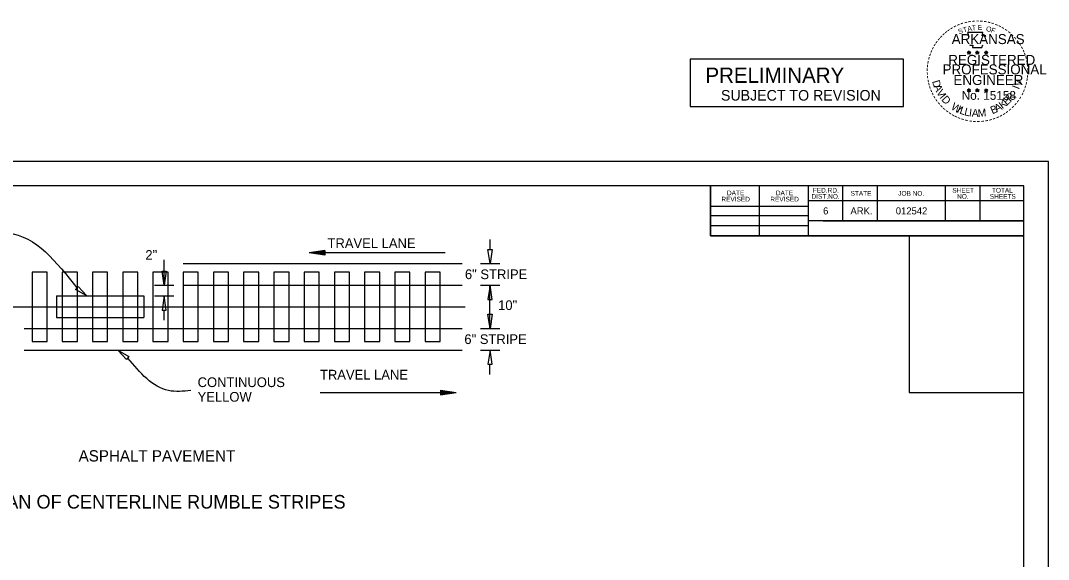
# Model space of a CAD drawing. Extents: x 1371343 to 1376243, y 378740 to 382184.
# Drawn here: x 1371995 to 1373043, y 381635 to 382184 of the extents above; entities that cross this region are included whole.
import ezdxf

# ---------------------------------------------------------------- set-up
doc = ezdxf.new("R2010")
doc.units = 0
for name, color, linetype in [('Default', 7, 'Continuous'), ('R_Border PE', 7, 'Continuous'), ('SHET_Annotations', 7, 'Continuous'), ('SHET_Border-Lines', 7, 'Continuous'), ('SHET_Border-Text', 7, 'Continuous'), ('SHET_Stamp-PE-Chief-Eng', 7, 'Continuous'), ('SHET_Stamp-Prelim', 7, 'Continuous'), ('SHET_Stamp-Seal', 7, 'Continuous')]:
    doc.layers.add(name, color=color, linetype=linetype)

msp = doc.modelspace()

# ---------------------------------------------------------------- linework, layer by layer
at = {"layer": 'Default'}
for p, q in [((1372473.6, 381960.9), (1372473.6, 381950.6)), ((1372305.1, 381949.6), (1372289.3, 381947.3)), ((1372427.9, 381947.3), (1372289.3, 381947.3)), ((1372305.1, 381944.9), (1372289.3, 381947.3)), ((1372305.1, 381949.2), (1372292, 381947.3)), ((1372305.1, 381945.3), (1372292, 381947.3)), ((1372305.1, 381948.8), (1372294.7, 381947.3)), ((1372305.1, 381945.7), (1372294.7, 381947.3)), ((1372305.1, 381948.4), (1372297.3, 381947.3)), ((1372305.1, 381946.1), (1372297.3, 381947.3)), ((1372305.1, 381948), (1372300, 381947.3)), ((1372305.1, 381946.5), (1372300, 381947.3)), ((1372305.1, 381947.6), (1372302.6, 381947.3)), ((1372305.1, 381946.9), (1372302.6, 381947.3)), ((1372305.1, 381949.6), (1372305.1, 381944.9)), ((1372141.5, 381914.2), (1372141.5, 381940.2)), ((1372161, 381936.2), (1372445.4, 381936.2)), ((1372463.8, 381936.2), (1372483.5, 381936.2)), ((1372131.6, 381914.2), (1372151.4, 381914.2)), ((1372161, 381914.2), (1372445.4, 381914.2)), ((1372463.8, 381914.2), (1372483.5, 381914.2)), ((1372473.6, 381870.1), (1372473.6, 381914.2)), ((1372031.7, 381903.2), (1372031.7, 381881.1)), ((1372031.7, 381903.2), (1372120.6, 381903.2)), ((1372120.6, 381903.2), (1372120.6, 381881.1)), ((1372131.6, 381903.2), (1372151.4, 381903.2)), ((1372161, 381903.7), (1372161, 381897.9)), ((1371839.4, 381892.1), (1372448.3, 381892.1)), ((1372031.7, 381881.1), (1372120.6, 381881.1)), ((1372141.5, 381878.4), (1372141.5, 381888.7)), ((1371998.8, 381870.1), (1372445.4, 381870.1)), ((1372463.8, 381870.1), (1372483.5, 381870.1)), ((1371998.8, 381848.1), (1372445.4, 381848.1)), ((1372463.8, 381848.1), (1372483.5, 381848.1)), ((1372473.6, 381823.3), (1372473.6, 381833.7)), ((1372300.4, 381804.9), (1372439, 381804.9)), ((1372423.2, 381807.2), (1372439, 381804.9)), ((1372423.2, 381807.2), (1372423.2, 381802.5)), ((1372423.2, 381806.8), (1372436.3, 381804.9)), ((1372423.2, 381806.4), (1372433.6, 381804.9)), ((1372423.2, 381806.1), (1372431, 381804.9)), ((1372423.2, 381805.6), (1372428.3, 381804.9)), ((1372423.2, 381805.2), (1372425.7, 381804.9)), ((1372423.2, 381802.5), (1372439, 381804.9)), ((1372423.2, 381804.1), (1372428.3, 381804.9)), ((1372423.2, 381803.3), (1372433.6, 381804.9)), ((1372423.2, 381802.9), (1372436.3, 381804.9)), ((1372423.2, 381803.7), (1372431, 381804.9)), ((1372423.2, 381804.5), (1372425.7, 381804.9))]:
    msp.add_line(p, q, dxfattribs=at)
for points in [[(1372677.8, 382096.3), (1372895.2, 382096.3), (1372895.2, 382144.9), (1372677.8, 382144.9)], [(1371342.9, 382040.5), (1371342.9, 380940.5), (1373042.9, 380940.5), (1373042.9, 382040.5)], [(1372471.4, 381950.6), (1372475.8, 381950.6), (1372473.7, 381936.2)], [(1372006.8, 381927.4), (1372006.8, 381856.9), (1372022.2, 381856.9), (1372022.2, 381927.4)], [(1372037.6, 381927.4), (1372037.6, 381856.9), (1372053, 381856.9), (1372053, 381927.4)], [(1372068.4, 381927.4), (1372068.4, 381856.9), (1372083.8, 381856.9), (1372083.8, 381927.4)], [(1372099.2, 381927.4), (1372099.2, 381856.9), (1372114.6, 381856.9), (1372114.6, 381927.4)], [(1372130.1, 381927.4), (1372130.1, 381856.9), (1372145.5, 381856.9), (1372145.5, 381927.4)], [(1372139.3, 381928.6), (1372143.6, 381928.6), (1372141.5, 381914.2)], [(1372160.9, 381927.4), (1372160.9, 381856.9), (1372176.3, 381856.9), (1372176.3, 381927.4)], [(1372191.7, 381927.4), (1372191.7, 381856.9), (1372207.1, 381856.9), (1372207.1, 381927.4)], [(1372222.5, 381927.4), (1372222.5, 381856.9), (1372237.9, 381856.9), (1372237.9, 381927.4)], [(1372253.3, 381927.4), (1372253.3, 381856.9), (1372268.8, 381856.9), (1372268.8, 381927.4)], [(1372284.2, 381927.4), (1372284.2, 381856.9), (1372299.6, 381856.9), (1372299.6, 381927.4)], [(1372315, 381927.4), (1372315, 381856.9), (1372330.4, 381856.9), (1372330.4, 381927.4)], [(1372345.8, 381927.4), (1372345.8, 381856.9), (1372361.2, 381856.9), (1372361.2, 381927.4)], [(1372376.6, 381927.4), (1372376.6, 381856.9), (1372392, 381856.9), (1372392, 381927.4)], [(1372407.5, 381927.4), (1372407.5, 381856.9), (1372422.9, 381856.9), (1372422.9, 381927.4)], [(1372051.2, 381909.9), (1372053.7, 381913), (1372062.8, 381903.2)], [(1372471.4, 381899.7), (1372475.8, 381899.7), (1372473.7, 381914.2)], [(1372139.3, 381888.7), (1372143.6, 381888.7), (1372141.5, 381903.2)], [(1372471.4, 381884.6), (1372475.8, 381884.6), (1372473.7, 381870.1)], [(1372105.6, 381841.4), (1372103.1, 381838.3), (1372094.1, 381848.1)], [(1372471.4, 381833.7), (1372475.8, 381833.7), (1372473.7, 381848.1)]]:
    msp.add_lwpolyline(points, close=True, dxfattribs=at)
for points in [[(1371964, 381967.4), (1371982.2, 381967.4), (1372052.5, 381911.4)], [(1372168.7, 381806.7), (1372146, 381806.7), (1372104.4, 381839.9)]]:
    msp.add_spline(points, degree=3, dxfattribs=at)
at = {"layer": 'R_Border PE'}
for p, q in [((1372961.9, 382153.3), (1372961.7, 382152)), ((1372961.9, 382151.4), (1372961.9, 382153.3)), ((1372961.9, 382153.3), (1372962.1, 382152)), ((1372970.4, 382153.3), (1372970.2, 382152)), ((1372970.4, 382151.4), (1372970.4, 382153.3)), ((1372970.4, 382153.3), (1372970.7, 382152)), ((1372979.4, 382153.2), (1372979.2, 382151.9)), ((1372979.4, 382151.4), (1372979.4, 382153.2)), ((1372979.4, 382153.2), (1372979.7, 382152)), ((1372960.1, 382152), (1372961.9, 382151.4)), ((1372960.1, 382152), (1372961.4, 382151.8)), ((1372960.1, 382152), (1372961.3, 382151.4)), ((1372960.8, 382149.9), (1372961.9, 382151.4)), ((1372960.8, 382149.9), (1372961.4, 382151.2)), ((1372960.8, 382149.9), (1372961.9, 382151)), ((1372963.7, 382152), (1372961.9, 382151.4)), ((1372963, 382149.9), (1372961.9, 382151.4)), ((1372963, 382149.9), (1372961.9, 382151)), ((1372963.7, 382152), (1372962.2, 382151.7)), ((1372963, 382149.9), (1372962.3, 382151.4)), ((1372963.7, 382152), (1372962.6, 382151.5)), ((1372968.6, 382152), (1372970.4, 382151.4)), ((1372968.6, 382152), (1372969.9, 382151.8)), ((1372968.6, 382152), (1372969.8, 382151.4)), ((1372969.3, 382149.9), (1372970.4, 382151.4)), ((1372969.3, 382149.9), (1372970, 382151.2)), ((1372969.3, 382149.9), (1372970.4, 382151)), ((1372972.2, 382152), (1372970.4, 382151.4)), ((1372971.5, 382149.9), (1372970.4, 382151.4)), ((1372971.5, 382149.9), (1372970.4, 382151)), ((1372972.2, 382152), (1372970.7, 382151.7)), ((1372971.5, 382149.9), (1372970.8, 382151.4)), ((1372972.2, 382152), (1372971.1, 382151.5)), ((1372977.6, 382151.9), (1372979.4, 382151.4)), ((1372977.6, 382151.9), (1372978.9, 382151.7)), ((1372977.6, 382151.9), (1372978.8, 382151.3)), ((1372978.3, 382149.9), (1372979.4, 382151.4)), ((1372978.3, 382149.9), (1372978.9, 382151.1)), ((1372978.3, 382149.9), (1372979.4, 382151)), ((1372981.2, 382151.9), (1372979.4, 382151.4)), ((1372980.5, 382149.9), (1372979.4, 382151.4)), ((1372980.5, 382149.9), (1372979.4, 382150.9)), ((1372981.2, 382151.9), (1372979.7, 382151.7)), ((1372980.5, 382149.9), (1372979.8, 382151.3)), ((1372981.2, 382151.9), (1372980.1, 382151.4)), ((1372960.1, 382113.4), (1372961.9, 382112.8)), ((1372960.1, 382113.4), (1372961.4, 382113.1)), ((1372960.1, 382113.4), (1372961.3, 382112.8)), ((1372960.8, 382111.3), (1372961.9, 382112.8)), ((1372960.8, 382111.3), (1372961.4, 382112.5)), ((1372960.8, 382111.3), (1372961.9, 382112.4)), ((1372961.9, 382114.7), (1372961.7, 382113.4)), ((1372961.9, 382112.8), (1372961.9, 382114.7)), ((1372961.9, 382114.7), (1372962.1, 382113.4)), ((1372963.6, 382113.4), (1372961.9, 382112.8)), ((1372963, 382111.3), (1372961.9, 382112.8)), ((1372963, 382111.3), (1372961.9, 382112.4)), ((1372963.6, 382113.4), (1372962.2, 382113.1)), ((1372963, 382111.3), (1372962.3, 382112.8)), ((1372963.6, 382113.4), (1372962.6, 382112.9)), ((1372968.6, 382113.4), (1372970.4, 382112.8)), ((1372968.6, 382113.4), (1372969.9, 382113.1)), ((1372968.6, 382113.4), (1372969.8, 382112.8)), ((1372969.3, 382111.3), (1372970.4, 382112.8)), ((1372969.3, 382111.3), (1372969.9, 382112.5)), ((1372969.3, 382111.3), (1372970.4, 382112.4)), ((1372970.4, 382114.7), (1372970.2, 382113.4)), ((1372970.4, 382112.8), (1372970.4, 382114.7)), ((1372970.4, 382114.7), (1372970.6, 382113.4)), ((1372972.2, 382113.4), (1372970.4, 382112.8)), ((1372971.5, 382111.3), (1372970.4, 382112.8)), ((1372971.5, 382111.3), (1372970.4, 382112.4)), ((1372972.2, 382113.4), (1372970.7, 382113.1)), ((1372971.5, 382111.3), (1372970.8, 382112.8)), ((1372972.2, 382113.4), (1372971.1, 382112.9)), ((1372977.6, 382113.3), (1372979.4, 382112.8)), ((1372977.6, 382113.3), (1372978.9, 382113.1)), ((1372977.6, 382113.3), (1372978.8, 382112.7)), ((1372978.3, 382111.2), (1372979.4, 382112.8)), ((1372978.3, 382111.2), (1372978.9, 382112.5)), ((1372978.3, 382111.2), (1372979.4, 382112.3)), ((1372979.4, 382114.6), (1372979.2, 382113.3)), ((1372979.4, 382112.8), (1372979.4, 382114.6)), ((1372979.4, 382114.6), (1372979.6, 382113.3)), ((1372981.2, 382113.3), (1372979.4, 382112.8)), ((1372980.5, 382111.2), (1372979.4, 382112.8)), ((1372980.5, 382111.2), (1372979.4, 382112.3)), ((1372981.2, 382113.3), (1372979.7, 382113.1)), ((1372980.5, 382111.2), (1372979.8, 382112.7)), ((1372981.2, 382113.3), (1372980.1, 382112.8))]:
    msp.add_line(p, q, dxfattribs=at)
for points in [[(1372960.3, 382171.8), (1372961.7, 382167.6)], [(1372978.2, 382167.1), (1372979, 382168.5), (1372975.5, 382168.4), (1372976.2, 382171.8), (1372960.3, 382171.8)], [(1372962.8, 382159.4), (1372962.8, 382159), (1372965.7, 382158.9), (1372965.4, 382156.5), (1372975, 382156.5), (1372976, 382159.2)], [(1372970.4, 382153.3), (1372971.5, 382149.9), (1372968.6, 382152), (1372972.2, 382152), (1372969.3, 382149.9), (1372970.4, 382153.3)], [(1372979.4, 382153.2), (1372980.5, 382149.9), (1372977.6, 382151.9), (1372981.2, 382151.9), (1372978.3, 382149.9), (1372979.4, 382153.2)], [(1372961.9, 382114.7), (1372963, 382111.3), (1372960.1, 382113.4), (1372963.6, 382113.4), (1372960.8, 382111.3), (1372961.9, 382114.7)], [(1372970.4, 382114.7), (1372971.5, 382111.3), (1372968.6, 382113.4), (1372972.2, 382113.4), (1372969.3, 382111.3), (1372970.4, 382114.7)], [(1372979.4, 382114.6), (1372980.5, 382111.2), (1372977.6, 382113.3), (1372981.2, 382113.3), (1372978.3, 382111.2), (1372979.4, 382114.6)]]:
    msp.add_lwpolyline(points, dxfattribs=at)
for centre, radius in [((1372961.9, 382151.4), 0.878), ((1372961.9, 382151.4), 0.737), ((1372961.9, 382151.4), 0.59), ((1372961.9, 382151.4), 0.505), ((1372961.9, 382151.4), 0.381), ((1372961.9, 382151.4), 0.253), ((1372961.9, 382151.4), 0.151), ((1372970.4, 382151.4), 0.878), ((1372970.4, 382151.4), 0.737), ((1372970.4, 382151.4), 0.59), ((1372970.4, 382151.4), 0.505), ((1372970.4, 382151.4), 0.381), ((1372970.4, 382151.4), 0.253), ((1372970.4, 382151.4), 0.151), ((1372979.4, 382151.4), 0.878), ((1372979.4, 382151.4), 0.737), ((1372979.4, 382151.4), 0.59), ((1372979.4, 382151.4), 0.505), ((1372979.4, 382151.4), 0.381), ((1372979.4, 382151.4), 0.253), ((1372979.4, 382151.4), 0.151), ((1372961.9, 382112.8), 0.878), ((1372961.9, 382112.8), 0.737), ((1372961.9, 382112.8), 0.59), ((1372961.9, 382112.8), 0.505), ((1372961.9, 382112.8), 0.381), ((1372961.9, 382112.8), 0.253), ((1372961.9, 382112.8), 0.151), ((1372970.4, 382112.8), 0.878), ((1372970.4, 382112.8), 0.737), ((1372970.4, 382112.8), 0.59), ((1372970.4, 382112.8), 0.505), ((1372970.4, 382112.8), 0.381), ((1372970.4, 382112.8), 0.253), ((1372970.4, 382112.8), 0.151), ((1372979.4, 382112.8), 0.878), ((1372979.4, 382112.8), 0.737), ((1372979.4, 382112.8), 0.59), ((1372979.4, 382112.8), 0.505), ((1372979.4, 382112.8), 0.381), ((1372979.4, 382112.8), 0.253), ((1372979.4, 382112.8), 0.151)]:
    msp.add_circle(centre, radius, dxfattribs=at)
at = {"layer": 'SHET_Border-Lines'}
for p, q in [((1372698.5, 381964.6), (1372698.5, 382015.5)), ((1372748.3, 381964.6), (1372748.3, 382015.5)), ((1372798.1, 382015.5), (1372798.1, 381964.6)), ((1372833, 382015.5), (1372833, 381979.7)), ((1372868.4, 382015.5), (1372868.4, 381979.7)), ((1372937.6, 382015.5), (1372937.6, 381979.7)), ((1372973, 382015.5), (1372973, 381979.7)), ((1373017.9, 382000.3), (1372798.1, 382000.3)), ((1373017.9, 382000.4), (1373017.9, 382000.4)), ((1372698.5, 381994.8), (1372798.1, 381994.8)), ((1372698.5, 381985.2), (1372798.1, 381985.2)), ((1372698.5, 381975.2), (1372798.1, 381975.2)), ((1373017.9, 381979.7), (1372798.1, 381979.7)), ((1372813.2, 381979.7), (1373017.9, 381979.7)), ((1373017.9, 381964.6), (1372698.5, 381964.6))]:
    msp.add_line(p, q, dxfattribs=at)
for points in [[(1371342.9, 380940.5), (1373042.9, 380940.5), (1373042.9, 382040.5), (1371342.9, 382040.5)], [(1371367.9, 380965.5), (1373017.9, 380965.5), (1373017.9, 382015.5), (1371367.9, 382015.5)], [(1372698.5, 381964.6), (1373017.9, 381964.6), (1373017.9, 382015.5), (1372698.5, 382015.5)]]:
    msp.add_lwpolyline(points, close=True, dxfattribs=at)
at = {"layer": 'SHET_Stamp-PE-Chief-Eng'}
msp.add_lwpolyline([(1372961.9, 382153.3), (1372963, 382149.9), (1372960.1, 382152), (1372963.7, 382152), (1372960.8, 382149.9), (1372961.9, 382153.3)], dxfattribs=at)
at = {"layer": 'SHET_Stamp-Prelim'}
msp.add_lwpolyline([(1372907.9, 381964.5), (1372908.1, 381964.5), (1372908.1, 381964.6), (1372907.9, 381964.6)], close=True, dxfattribs=at)
at = {"layer": 'SHET_Stamp-Seal'}
msp.add_lwpolyline([(1372900.9, 381804.8), (1373017.9, 381804.8), (1373017.9, 381964.6), (1372900.9, 381964.6)], close=True, dxfattribs=at)

# ---------------------------------------------------------------- texts
at = {"layer": 'Default'}
for s, height, p in [('PRELIMINARY', 15.6, (1372693.3, 382120.6)), ('SUBJECT TO REVISION', 10.8, (1372709.1, 382102.5)), ('TRAVEL LANE', 9.9, (1372308, 381952.1)), ('2"', 9.9, (1372122.3, 381940.1)), ('6" STRIPE', 9.9, (1372448.1, 381920.4)), ('10"', 9.9, (1372481.9, 381888.9)), ('6" STRIPE', 9.9, (1372447.5, 381854.2)), ('CONTINUOUS ', 9.9, (1372175.6, 381810.3)), ('TRAVEL LANE', 9.9, (1372300.3, 381818)), ('YELLOW', 9.9, (1372175.6, 381795.4)), ('ASPHALT PAVEMENT', 11.55, (1372054.3, 381734.4)), ('LOCATION PLAN OF CENTERLINE RUMBLE STRIPES', 13.86, (1371857.9, 381686.4))]:
    msp.add_text(s, height=height, dxfattribs=at).set_placement(p)
at = {"layer": 'R_Border PE'}
for s, height, rotation, p in [('-', 8.16, 36.2317, (1372941.5, 382170.6)), ('-', 8.16, 34.0636, (1372944.4, 382172.6)), ('-', 8.16, 28.7918, (1372947.5, 382174.5)), ('-', 8.16, 24.3072, (1372950.7, 382176.1)), ('S', 5.1, 21.594, (1372951.9, 382170.1)), ('-', 8.16, 19.1761, (1372953.9, 382177.5)), ('T', 5.1, 16.4036, (1372956.6, 382171.8)), ('-', 8.16, 13.6302, (1372957.8, 382178.7)), ('A', 5.1, 11.2132, (1372960.8, 382173.1)), ('-', 8.16, 10.2193, (1372961.2, 382179.6)), ('T', 5.1, 6.0228, (1372965.1, 382173.9)), ('-', 8.16, 5.8968, (1372964.9, 382180.1)), ('-', 8.16, 0.1862, (1372968.9, 382180.5)), ('E', 5.1, 0.8323, (1372970.8, 382174.5)), ('-', 8.16, 357.743, (1372972.6, 382180.4)), ('-', 8.16, 352.1617, (1372976.4, 382180.2)), ('O', 5.1, 350.4515, (1372979, 382173.4)), ('-', 8.16, 347.2049, (1372980, 382179.6)), ('F', 5.1, 340.0707, (1372983.8, 382172.3)), ('-', 8.16, 342.3362, (1372983.3, 382178.8)), ('-', 8.16, 337.8551, (1372987, 382177.6)), ('-', 8.16, 334.1211, (1372990.2, 382176.3)), ('-', 8.16, 329.6409, (1372993.2, 382174.8)), ('-', 8.16, 325.8627, (1372996.5, 382173)), ('-', 8.16, 50.6142, (1372932.5, 382161.7)), ('-', 8.16, 48.4231, (1372934.6, 382164.1)), ('-', 8.16, 42.9622, (1372936.8, 382166.6)), ('-', 8.16, 38.9507, (1372939.1, 382168.7)), ('-', 8.16, 320.5297, (1372999.6, 382170.8)), ('-', 8.16, 315.5786, (1373002.6, 382168.3)), ('-', 8.16, 309.8797, (1373005.5, 382165.5)), ('-', 8.16, 306.6522, (1373008.2, 382162.4)), ('-', 8.16, 67.7743, (1372925.8, 382149.8)), ('-', 8.16, 62.8713, (1372927.1, 382152.9)), ('-', 8.16, 58.0706, (1372928.7, 382156.1)), ('-', 8.16, 54.2325, (1372930.4, 382158.8)), ('-', 7.14, 303.6753, (1373010.7, 382159.5)), ('-', 8.16, 299.6684, (1373012.3, 382156.4)), ('-', 8.16, 294.6628, (1373014, 382153.3)), ('-', 8.16, 81.2013, (1372923, 382139.3)), ('-', 8.16, 75.461, (1372923.7, 382143)), ('-', 8.16, 72.3945, (1372924.7, 382146.6)), ('-', 8.16, 290.5728, (1373015.3, 382150.4)), ('-', 8.16, 285.1233, (1373016.5, 382147.4)), ('-', 8.16, 280.5493, (1373017.5, 382143.6)), ('-', 8.16, 89.0622, (1372922.5, 382132.2)), ('-', 8.16, 85.1863, (1372922.6, 382135.8)), ('-', 8.16, 276.5962, (1373018.3, 382139.7)), ('-', 8.16, 274.3301, (1373018.6, 382136)), ('-', 8.16, 269.9407, (1373018.8, 382132.8)), ('-', 8.16, 94.1959, (1372922.7, 382128.5)), ('-', 8.16, 98.9479, (1372923.1, 382125.1)), ('-', 8.16, 101.7149, (1372923.8, 382121.4)), ('D', 7.85, 286.2848, (1372924.2, 382122.1)), ('V', 7.85, 72.6573, (1373013.9, 382116.2)), ('-', 8.16, 260.9953, (1373018.3, 382126.1)), ('-', 8.16, 263.5172, (1373018.7, 382129.4)), ('-', 8.16, 105.4578, (1372924.6, 382118.4)), ('-', 8.16, 109.0874, (1372925.7, 382115.2)), ('-', 8.16, 114.0643, (1372927, 382112.1)), ('A', 7.85, 292.7835, (1372925.7, 382117)), ('V', 7.85, 300.7936, (1372928.3, 382111)), ('I', 7.85, 69.0301, (1373012.8, 382113.4)), ('-', 8.16, 247.8887, (1373015.7, 382115.5)), ('-', 8.16, 252.8681, (1373016.8, 382119)), ('-', 8.16, 255.7626, (1373017.8, 382122.6)), ('-', 8.16, 115.7289, (1372928.5, 382109)), ('-', 8.16, 120.4471, (1372930.3, 382106)), ('-', 8.16, 125.8934, (1372932.4, 382103.1)), ('-', 8.16, 130.7181, (1372934.8, 382100.3)), ('I', 7.85, 308.3502, (1372931.5, 382105.7)), ('D', 7.85, 311.9774, (1372933.3, 382103.3)), ('W', 7.85, 328.0731, (1372942.9, 382094.3)), ('K', 7.85, 36.9143, (1372996, 382093.6)), ('E', 7.85, 44.0175, (1373000.6, 382097.1)), ('R', 7.85, 50.3651, (1373004.4, 382100.7)), (',', 7.85, 57.4684, (1373008.1, 382105.2)), ('-', 8.16, 233.8452, (1373010.3, 382105.2)), ('-', 8.16, 239.0712, (1373012.4, 382108.5)), ('-', 8.16, 244.6197, (1373014.4, 382112.3)), ('-', 8.16, 134.2238, (1372937.4, 382097.5)), ('-', 8.16, 138.9338, (1372940.1, 382095.2)), ('-', 8.16, 144.6463, (1372942.9, 382093.1)), ('-', 8.16, 148.0898, (1372945.8, 382091.2)), ('I', 7.85, 336.6877, (1372949, 382090.7)), ('L', 7.85, 340.3149, (1372951.7, 382089.5)), ('L', 7.85, 346.6625, (1372956.6, 382087.7)), ('I', 7.85, 353.0101, (1372961.6, 382086.5)), ('A', 7.85, 356.6373, (1372964.6, 382086.1)), ('M', 7.85, 4.6473, (1372971.1, 382085.8)), ('B', 7.85, 22.8589, (1372985.7, 382088.5)), ('A', 7.85, 28.9042, (1372990.3, 382090.4)), ('-', 8.16, 215.7363, (1373000.2, 382094.4)), ('-', 8.16, 221.0851, (1373003, 382096.8)), ('-', 8.16, 225.7653, (1373005.7, 382099.4)), ('-', 8.16, 231.2538, (1373008.1, 382102.3)), ('-', 8.16, 151.5704, (1372948.7, 382089.5)), ('-', 8.16, 154.6002, (1372951.4, 382088.3)), ('-', 8.16, 158.5612, (1372954.6, 382087)), ('-', 8.16, 162.7983, (1372958.1, 382085.9)), ('-', 8.16, 167.5555, (1372961.7, 382085.1)), ('-', 8.16, 173.1155, (1372965.7, 382084.5)), ('-', 8.16, 176.5183, (1372969.5, 382084.2)), ('-', 8.16, 181.5918, (1372973.3, 382084.3)), ('-', 8.16, 185.8167, (1372977.4, 382084.7)), ('-', 8.16, 191.2858, (1372981.1, 382085.4)), ('-', 8.16, 195.4743, (1372984.9, 382086.4)), ('-', 8.16, 199.4643, (1372988.2, 382087.6)), ('-', 8.16, 204.2516, (1372991.5, 382089)), ('-', 8.16, 207.3568, (1372994.6, 382090.6)), ('-', 8.16, 212.2491, (1372997.5, 382092.4))]:
    msp.add_text(s, height=height, rotation=rotation, dxfattribs=at).set_placement(p)
for s, height, p in [('ARKANSAS', 10.2, (1372944.3, 382160.1)), ('REGISTERED', 10.2, (1372940.8, 382138.9)), ('PROFESSIONAL', 10.2, (1372935, 382129.2)), ('ENGINEER', 10.2, (1372946.1, 382118.4)), ('No. 15158', 8.96, (1372954.5, 382103.3)), ('AAMU', 0.000102, (1372970, 382085.7))]:
    msp.add_text(s, height=height, dxfattribs=at).set_placement(p)
at = {"layer": 'SHET_Annotations'}
for s, p in [('6', (1372813.2, 381986.4)), ('ARK.', (1372841.1, 381986.4)), ('012542', (1372887.3, 381986.4))]:
    msp.add_text(s, height=7.2, dxfattribs=at).set_placement(p)
at = {"layer": 'SHET_Border-Text'}
for s, p in [('DATE', (1372715.2, 382005.9)), ('DATE', (1372765, 382005.9)), ('DIST.NO.', (1372801.4, 382002.4)), ('FED.RD.', (1372802.7, 382008.6)), ('STATE', (1372841.2, 382005.5)), ('JOB NO.', (1372889.8, 382005.5)), ('SHEET', (1372944.9, 382008.6)), ('NO.', (1372949.8, 382002.4)), ('SHEETS', (1372983.1, 382002.4)), ('TOTAL', (1372985.3, 382008.6)), ('REVISED', (1372709.5, 381999.6)), ('REVISED', (1372759.4, 381999.6))]:
    msp.add_text(s, height=4.8, dxfattribs=at).set_placement(p)
at = {"layer": 'SHET_Stamp-Prelim'}
for s, height in [('PRELIMINARY', 0.013), ('SUBJECT TO REVISION', 0.009)]:
    msp.add_text(s, height=height, dxfattribs=at).set_placement((1372907.9, 381964.5))

doc.saveas('drawing.dxf')
